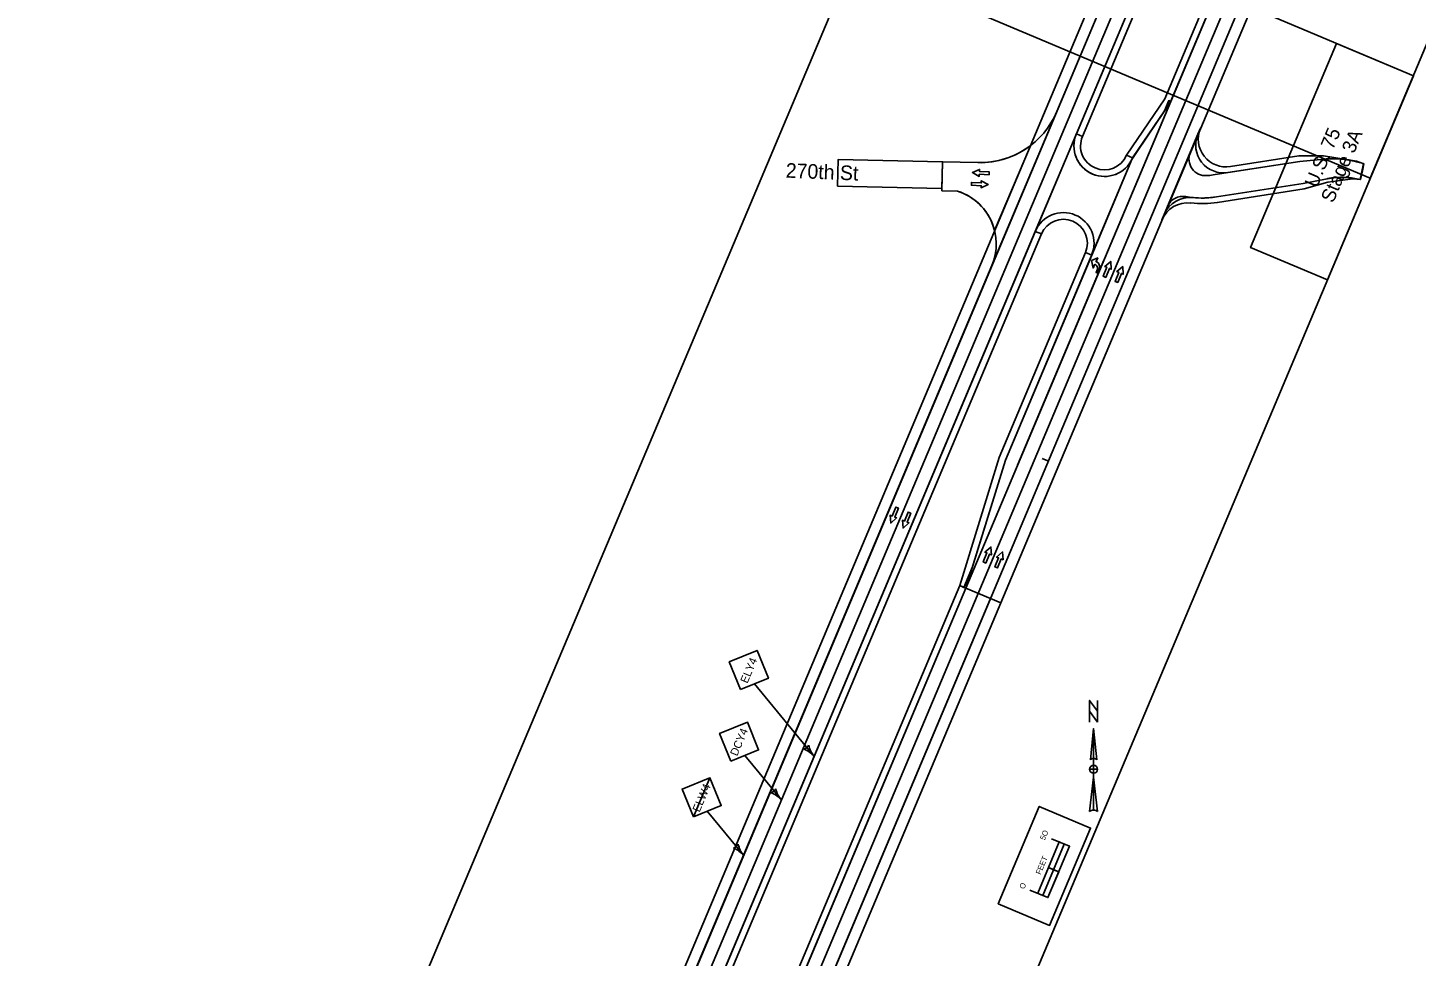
# Model space of a CAD drawing. Extents: x 14104283 to 14129344, y 8637090 to 8673339.
# Drawn here: x 14110477 to 14111726, y 8650038 to 8650873 of the extents above; entities that cross this region are included whole.
import ezdxf

# ---------------------------------------------------------------- set-up
doc = ezdxf.new("R2010")
doc.units = 0
for name, color, linetype in [('Cell', 7, 'Continuous'), ('Default', 7, 'Continuous'), ('dsnCellsNorthArrow', 7, 'Continuous'), ('dsnCellsScaleBlock', 7, 'Continuous'), ('dsnNonPlotable', 7, 'Continuous'), ('dsnPaintExistingBrokenLaneLineWhite', 7, 'Continuous'), ('dsnPaintExistingEdgeLineRightWhite', 7, 'Continuous'), ('dsnPaintExistingLaneLineWhite', 7, 'Continuous'), ('dsnPaintPlaceBrokenLineWhite', 7, 'Continuous'), ('dsnPaintPlaceEdgeLineLeftYellow', 7, 'Continuous'), ('dsnPaintPlaceEdgeLineRightWhite', 7, 'Continuous'), ('dsnShadingGranular', 7, 'Continuous'), ('dsnShadingPaved', 7, 'Continuous'), ('dsnStdLabel', 7, 'Continuous'), ('dsnStgShadingPrevPav', 7, 'Continuous'), ('dsnTextFinalPlan', 7, 'Continuous'), ('dsnTextOverlapEven', 7, 'Continuous'), ('TextAlignmentLrg', 7, 'Continuous')]:
    doc.layers.add(name, color=color, linetype=linetype)

msp = doc.modelspace()

# ---------------------------------------------------------------- linework, layer by layer
at = {"layer": 'Cell'}
for p, q in [((14111437.4, 8650659.6), (14111437.1, 8650659.8)), ((14111438.2, 8650662.2), (14111438.4, 8650662.1))]:
    msp.add_line(p, q, dxfattribs=at)
for points in [[(14111342.1, 8650742.9), (14111342, 8650740.4), (14111333.2, 8650740.8), (14111333.1, 8650738.9), (14111327, 8650742.3), (14111333.4, 8650745.1), (14111333.3, 8650743.3)], [(14111326.1, 8650730.9), (14111326.2, 8650733.4), (14111335, 8650733), (14111335, 8650734.9), (14111341.2, 8650731.5), (14111334.8, 8650728.6), (14111334.9, 8650730.5)], [(14111446.9, 8650648), (14111444.5, 8650649), (14111447.9, 8650657.1), (14111446.1, 8650657.8), (14111451.4, 8650662.4), (14111451.9, 8650655.4), (14111450.2, 8650656.1)], [(14111457.7, 8650643.5), (14111455.4, 8650644.4), (14111458.7, 8650652.5), (14111456.9, 8650653.2), (14111462.2, 8650657.8), (14111462.7, 8650650.9), (14111461, 8650651.6)], [(14111258.1, 8650441.5), (14111260.4, 8650440.5), (14111257.1, 8650432.4), (14111258.8, 8650431.7), (14111253.5, 8650427.1), (14111253, 8650434.1), (14111254.7, 8650433.4)], [(14111269.2, 8650437), (14111271.5, 8650436), (14111268.2, 8650427.9), (14111269.9, 8650427.2), (14111264.6, 8650422.6), (14111264.1, 8650429.6), (14111265.8, 8650428.9)], [(14111339, 8650391.1), (14111336.7, 8650392.1), (14111340.1, 8650400.2), (14111338.3, 8650400.9), (14111343.6, 8650405.5), (14111344.1, 8650398.5), (14111342.4, 8650399.2)], [(14111349.6, 8650386.7), (14111347.2, 8650387.7), (14111350.6, 8650395.8), (14111348.8, 8650396.5), (14111354.1, 8650401.1), (14111354.6, 8650394.1), (14111352.9, 8650394.8)]]:
    msp.add_lwpolyline(points, close=True, dxfattribs=at)
for points in [[(14111333.3, 8650743.3), (14111333.4, 8650745.1), (14111327, 8650742.3), (14111333.1, 8650738.9), (14111333.2, 8650740.8), (14111342, 8650740.4), (14111342.1, 8650742.9), (14111333.3, 8650743.3)], [(14111334.9, 8650730.5), (14111334.8, 8650728.6), (14111341.2, 8650731.5), (14111335, 8650734.9), (14111335, 8650733), (14111326.2, 8650733.4), (14111326.1, 8650730.9), (14111334.9, 8650730.5)], [(14111434, 8650663.3), (14111439.8, 8650665.5), (14111438.2, 8650662.2)], [(14111434, 8650663.3), (14111439.8, 8650665.5), (14111438.2, 8650662.2)], [(14111437.1, 8650659.8), (14111435.6, 8650656.4), (14111434, 8650663.3)], [(14111437.1, 8650659.8), (14111435.6, 8650656.4), (14111434, 8650663.3)], [(14111437.4, 8650659.6), (14111437.1, 8650659.8)], [(14111438.2, 8650662.2), (14111438.4, 8650662.1)], [(14111450.2, 8650656.1), (14111451.9, 8650655.4), (14111451.4, 8650662.4), (14111446.1, 8650657.8), (14111447.9, 8650657.1), (14111444.5, 8650649), (14111446.9, 8650648), (14111450.2, 8650656.1)], [(14111461, 8650651.6), (14111462.7, 8650650.9), (14111462.2, 8650657.8), (14111456.9, 8650653.2), (14111458.7, 8650652.5), (14111455.4, 8650644.4), (14111457.7, 8650643.5), (14111461, 8650651.6)], [(14111441, 8650655.3), (14111439.7, 8650651.9), (14111438.3, 8650652.5), (14111439.3, 8650654.9)], [(14111441, 8650655.3), (14111439.7, 8650651.9), (14111438.3, 8650652.5), (14111439.3, 8650654.9)], [(14111254.7, 8650433.4), (14111253, 8650434.1), (14111253.5, 8650427.1), (14111258.8, 8650431.7), (14111257.1, 8650432.4), (14111260.4, 8650440.5), (14111258.1, 8650441.5), (14111254.7, 8650433.4)], [(14111265.8, 8650428.9), (14111264.1, 8650429.6), (14111264.6, 8650422.6), (14111269.9, 8650427.2), (14111268.2, 8650427.9), (14111271.5, 8650436), (14111269.2, 8650437), (14111265.8, 8650428.9)], [(14111342.4, 8650399.2), (14111344.1, 8650398.5), (14111343.6, 8650405.5), (14111338.3, 8650400.9), (14111340.1, 8650400.2), (14111336.7, 8650392.1), (14111339, 8650391.1), (14111342.4, 8650399.2)], [(14111352.9, 8650394.8), (14111354.6, 8650394.1), (14111354.1, 8650401.1), (14111348.8, 8650396.5), (14111350.6, 8650395.8), (14111347.2, 8650387.7), (14111349.6, 8650386.7), (14111352.9, 8650394.8)]]:
    msp.add_lwpolyline(points, dxfattribs=at)
for centre, major_axis in [((14111436, 8650656.2), (-1.38, -3.41)), ((14111436, 8650656.2), (-1.38, -3.41)), ((14111436.4, 8650657.2), (-1.97, -4.87)), ((14111436.4, 8650657.2), (-1.97, -4.87))]:
    msp.add_ellipse(centre, major_axis=major_axis, ratio=0.9474, start_param=1.570796, end_param=3.141593, dxfattribs=at)
at = {"layer": 'Default'}
for points in [[(14118413.2, 8667444.3), (14110818.4, 8649409.2), (14109142.6, 8645431.4)], [(14109164.7, 8645422.1), (14110840.5, 8649399.8), (14118435.4, 8667434.9)]]:
    msp.add_lwpolyline(points, dxfattribs=at)
at = {"layer": 'dsnCellsNorthArrow'}
for p, q in [((14111436, 8650242.3), (14111438.8, 8650214.1)), ((14111436, 8650242.3), (14111436, 8650169)), ((14111433.2, 8650214.1), (14111433.2, 8650214.1)), ((14111433.3, 8650214.4), (14111433.8, 8650215)), ((14111432.4, 8650167.6), (14111436, 8650198.6)), ((14111436, 8650202.1), (14111436, 8650202.1))]:
    msp.add_line(p, q, dxfattribs=at)
msp.add_lwpolyline([(14111439.5, 8650247.9), (14111432.4, 8650257.8), (14111432.4, 8650267.6), (14111439.5, 8650257.8)], close=True, dxfattribs=at)
for points in [[(14111432.4, 8650247.9), (14111432.4, 8650267.6), (14111439.5, 8650257.8), (14111439.5, 8650267.6)], [(14111433.2, 8650214.1), (14111436, 8650242.3), (14111436, 8650215.5)], [(14111439.5, 8650205.7), (14111436, 8650205.7), (14111436, 8650209.2)], [(14111436, 8650202.1), (14111436, 8650205.7), (14111432.4, 8650205.7)], [(14111436, 8650169), (14111436, 8650198.6), (14111439.5, 8650167.6)]]:
    msp.add_lwpolyline(points, dxfattribs=at)
for centre, radius, start, end in [((14111436, 8650205.7), 3.52, 90, 180), ((14111436, 8650212), 3.52, 90.0204, 143.1257), ((14111436, 8650212), 3.52, 36.8481, 90.0218), ((14111436, 8650205.7), 3.52, 0, 90), ((14111436, 8650205.7), 3.52, 180, 270), ((14111436, 8650205.7), 3.52, 270, 360), ((14111436, 8650163.9), 5.1, 89.9894, 133.619), ((14111436, 8650163.9), 5.11, 46.4021, 90.0006)]:
    msp.add_arc(centre, radius, start, end, dxfattribs=at)
at = {"layer": 'dsnCellsScaleBlock'}
msp.add_line((14111404.7, 8650113.3), (14111395.5, 8650117.2), dxfattribs=at)
msp.add_line((14111404.7, 8650113.3), (14111395.5, 8650117.2), dxfattribs=at)
for points in [[(14111396.4, 8650065.3), (14111350.3, 8650084.7), (14111387.2, 8650172.2), (14111433.3, 8650152.8)], [(14111350.3, 8650084.7), (14111387.2, 8650172.2), (14111433.3, 8650152.8), (14111396.4, 8650065.3)], [(14111396.4, 8650065.3), (14111350.3, 8650084.7), (14111387.2, 8650172.2), (14111433.3, 8650152.8)], [(14111400, 8650115.3), (14111409.7, 8650138.3), (14111405.2, 8650140.3), (14111395.5, 8650117.2)], [(14111395, 8650090.3), (14111404.7, 8650113.3), (14111400, 8650115.3), (14111390.3, 8650092.2)]]:
    msp.add_lwpolyline(points, close=True, dxfattribs=at)
for points in [[(14111378.8, 8650097.1), (14111395, 8650090.3), (14111414.4, 8650136.4), (14111398.3, 8650143.2)], [(14111385.8, 8650094.2), (14111405.2, 8650140.3)]]:
    msp.add_lwpolyline(points, dxfattribs=at)
at = {"layer": 'dsnNonPlotable'}
for points in [[(14111219.5, 8650933.3), (14111828.1, 8652377.8), (14112293.5, 8652181.8), (14111684.9, 8650737.2)], [(14110649.8, 8649580.9), (14111258.3, 8651025.5), (14111723.7, 8650829.4), (14111115.1, 8649384.9)]]:
    msp.add_lwpolyline(points, close=True, dxfattribs=at)
at = {"layer": 'dsnPaintExistingBrokenLaneLineWhite'}
msp.add_line((14110829.5, 8649404.5), (14118424.3, 8667439.6), dxfattribs=at)
at = {"layer": 'dsnPaintExistingEdgeLineRightWhite'}
msp.add_line((14110924.4, 8649364.5), (14118874.7, 8668243.7), dxfattribs=at)
at = {"layer": 'dsnPaintExistingLaneLineWhite'}
msp.add_line((14111367.7, 8650479.1), (14111445.3, 8650663.4), dxfattribs=at)
at = {"layer": 'dsnPaintPlaceBrokenLineWhite'}
msp.add_line((14110913.3, 8649369.2), (14114932.5, 8658913.4), dxfattribs=at)
at = {"layer": 'dsnPaintPlaceEdgeLineLeftYellow'}
for p, q in [((14113594.8, 8655940.3), (14111420.5, 8650777)), ((14111505.3, 8650805.9), (14113533.3, 8655621.7)), ((14111470.9, 8650755.1), (14111505.3, 8650805.9)), ((14111356.7, 8650483.8), (14111434.3, 8650668.1)), ((14111321.1, 8650368.5), (14111356.7, 8650483.8)), ((14110902.3, 8649373.8), (14111321.1, 8650368.5))]:
    msp.add_line(p, q, dxfattribs=at)
msp.add_lwpolyline([(14111383.6, 8650689.4), (14110840.5, 8649399.8), (14109233.5, 8645585.3)], dxfattribs=at)
for centre, start, end in [((14111445.8, 8650766.3), 157.1633, 335.8501), ((14111408.9, 8650678.8), 67.1633, 156.8935), ((14111408.9, 8650678.8), 337.1465, 67.1633)]:
    msp.add_arc(centre, 27.5, start, end, dxfattribs=at)
at = {"layer": 'dsnPaintPlaceEdgeLineRightWhite'}
msp.add_line((14113555.5, 8655908.7), (14111402.9, 8650797.1), dxfattribs=at)
msp.add_lwpolyline([(14111344.6, 8650658.6), (14110818.4, 8649409.2), (14109217, 8645608.1)], dxfattribs=at)
at = {"layer": 'dsnShadingGranular'}
msp.add_line((14111523, 8650760.3), (14111502.5, 8650711.7), dxfattribs=at)
at = {"layer": 'dsnShadingPaved'}
for p, q in [((14111505.5, 8650806.3), (14113533.3, 8655621.7)), ((14113555.5, 8655612.4), (14110924.4, 8649364.5)), ((14111321.1, 8650368.5), (14111505.5, 8650806.3)), ((14111505.3, 8650805.7), (14111321.1, 8650368.5)), ((14111402.9, 8650797.1), (14111344.6, 8650658.6)), ((14111470.6, 8650754.6), (14111505.3, 8650805.7)), ((14111383.6, 8650689.4), (14111420.5, 8650777)), ((14111299.6, 8650726), (14111300.2, 8650752)), ((14111300.2, 8650752), (14111332, 8650751.3)), ((14111313.6, 8650725.7), (14111299.6, 8650726)), ((14111356.7, 8650483.8), (14111434.3, 8650668.1)), ((14111321.1, 8650368.5), (14111356.7, 8650483.8)), ((14110902.3, 8649373.8), (14111321.1, 8650368.5))]:
    msp.add_line(p, q, dxfattribs=at)
for centre, radius, start, end in [((14111333.8, 8650826.2), 75, 268.6633, 337.1633), ((14111445.8, 8650766.3), 27.5, 157.1801, 247.1633), ((14111445.8, 8650766.3), 27.5, 247.1633, 335.8501), ((14111298.5, 8650678), 50, 337.1633, 72.4031), ((14111408.9, 8650678.8), 27.5, 67.1633, 156.8935), ((14111408.9, 8650678.8), 27.5, 337.1465, 67.1633)]:
    msp.add_arc(centre, radius, start, end, dxfattribs=at)
at = {"layer": 'dsnStdLabel'}
for p, q in [((14111131, 8650282.4), (14111184.8, 8650217.3)), ((14111122.2, 8650218), (14111155.2, 8650178.1)), ((14111076.1, 8650162.8), (14111090.9, 8650198)), ((14111088.6, 8650167.9), (14111121.2, 8650128.3))]:
    msp.add_line(p, q, dxfattribs=at)
for points in [[(14111118.5, 8650277.3), (14111143.5, 8650287.5), (14111133.3, 8650312.5), (14111108.3, 8650302.3)], [(14111109.7, 8650212.9), (14111134.7, 8650223.1), (14111124.6, 8650248.1), (14111099.6, 8650237.9)], [(14111076.1, 8650162.8), (14111101.1, 8650173), (14111090.9, 8650198), (14111065.9, 8650187.8)]]:
    msp.add_lwpolyline(points, close=True, dxfattribs=at)
for centre, radius, start, end in [((14111172.2, 8650231.9), 8.86, 292.8385, 328.307), ((14111167.3, 8650202.4), 22.9, 40.5727, 68.6439), ((14111202.2, 8650232.2), 22.9, 192.5015, 220.5728), ((14111142.7, 8650192.7), 8.86, 292.8385, 328.307), ((14111137.8, 8650163.1), 22.9, 40.5727, 68.6439), ((14111172.6, 8650193), 22.9, 192.5015, 220.5728), ((14111108.7, 8650143), 8.86, 292.8385, 328.307), ((14111103.8, 8650113.4), 22.9, 40.5727, 68.6439), ((14111138.7, 8650143.3), 22.9, 192.5015, 220.5728)]:
    msp.add_arc(centre, radius, start, end, dxfattribs=at)
at = {"layer": 'dsnStgShadingPrevPav'}
for p, q in [((14110809.2, 8649413), (14118404, 8667448.1)), ((14118413.2, 8667444.3), (14110818.4, 8649409.2)), ((14113594.8, 8655940.3), (14111420.5, 8650777)), ((14111402.9, 8650797.1), (14113555.5, 8655908.7)), ((14113533.3, 8655621.7), (14111505.5, 8650806.3)), ((14111352.5, 8650355.3), (14113564.7, 8655608.5)), ((14111505.5, 8650806.3), (14111321.1, 8650368.5)), ((14111344.6, 8650658.6), (14111402.9, 8650797.1)), ((14111383.6, 8650689.4), (14111420.5, 8650777)), ((14111420.5, 8650777), (14111383.6, 8650689.4)), ((14111420.5, 8650777), (14111426, 8650774.7)), ((14111529.9, 8650776.7), (14111523, 8650760.3)), ((14111532.2, 8650782.1), (14111529.9, 8650776.7)), ((14111379.2, 8650766.5), (14111347, 8650690.1)), ((14111465.6, 8650758), (14111471.1, 8650755.6)), ((14111523, 8650760.3), (14111502.5, 8650711.7)), ((14111620.7, 8650757.3), (14111559.1, 8650747.7)), ((14111642.9, 8650757.4), (14111620.7, 8650757.3)), ((14111299.6, 8650726), (14111300.2, 8650752)), ((14111300.2, 8650752), (14111332, 8650751.3)), ((14111471.1, 8650755.6), (14111434.3, 8650668.1)), ((14111621.5, 8650752.4), (14111543.5, 8650740.2)), ((14111556.8, 8650742.3), (14111621.5, 8650752.4)), ((14111643.4, 8650754.4), (14111621.5, 8650752.4)), ((14111621.5, 8650752.4), (14111643.4, 8650754.4)), ((14111678.8, 8650750.4), (14111672.4, 8650752.1)), ((14111672.4, 8650752.1), (14111678.8, 8650750.4)), ((14111675.9, 8650736.2), (14111678.8, 8650750.4)), ((14111678.8, 8650750.4), (14111677.5, 8650744)), ((14111677.8, 8650744), (14111679, 8650750.3)), ((14111543.5, 8650740.2), (14111556.8, 8650742.3)), ((14111546.6, 8650720.4), (14111624.6, 8650732.6)), ((14111624.6, 8650732.6), (14111546.6, 8650720.4)), ((14111624.6, 8650732.6), (14111646.1, 8650736.8)), ((14111646.1, 8650736.8), (14111624.6, 8650732.6)), ((14111625.4, 8650727.7), (14111646.6, 8650733.8)), ((14111669.4, 8650737.2), (14111675.9, 8650736.2)), ((14111675.9, 8650736.2), (14111669.4, 8650737.2)), ((14111677.5, 8650744), (14111675.9, 8650736.2)), ((14111676.2, 8650736.1), (14111677.8, 8650744)), ((14111677.8, 8650744), (14111677.5, 8650744)), ((14111677.5, 8650744), (14111677.8, 8650744)), ((14111313.6, 8650725.7), (14111299.6, 8650726)), ((14111547.4, 8650715.5), (14111625.4, 8650727.7)), ((14111502.5, 8650711.7), (14111499.6, 8650704.6)), ((14111499.6, 8650704.6), (14111497.5, 8650699.8)), ((14111389.1, 8650687.1), (14111383.6, 8650689.4)), ((14111434.3, 8650668.1), (14111428.7, 8650670.4)), ((14111321.1, 8650368.5), (14111352.5, 8650355.3))]:
    msp.add_line(p, q, dxfattribs=at)
for points in [[(14113600.3, 8655938), (14111426, 8650774.7), (14111420.5, 8650777), (14113594.8, 8655940.3)], [(14111465.6, 8650758), (14111500, 8650808.6), (14113527.8, 8655624.1), (14113533.3, 8655621.7), (14111505.5, 8650806.3), (14111503.6, 8650807.1), (14111499.8, 8650797.8), (14111471.1, 8650755.6)], [(14111321.1, 8650368.5), (14111319.3, 8650369.3), (14111327.1, 8650387.7), (14111356.7, 8650483.8), (14111471.1, 8650755.6), (14111499.8, 8650797.8), (14111503.6, 8650807.1), (14111505.5, 8650806.3)], [(14111299.6, 8650728), (14111205.7, 8650730.2), (14111206.3, 8650754.2), (14111300.2, 8650752)], [(14109239, 8645583), (14111389.1, 8650687.1), (14111383.6, 8650689.4), (14109233.5, 8645585.3)], [(14111315.6, 8650370.9), (14111351.1, 8650486.1), (14111428.7, 8650670.4), (14111434.3, 8650668.1), (14111356.7, 8650483.8), (14111327.1, 8650387.7), (14111319.3, 8650369.3)], [(14110622.7, 8648725.7), (14111315.6, 8650370.9), (14111321.1, 8650368.5), (14110628.3, 8648723.4)], [(14110902.3, 8649373.8), (14110924.4, 8649364.5), (14111343.3, 8650359.2), (14111321.1, 8650368.5)], [(14110933.6, 8649360.6), (14111352.5, 8650355.3), (14111343.3, 8650359.2), (14110924.4, 8649364.5)]]:
    msp.add_lwpolyline(points, close=True, dxfattribs=at)
for points in [[(14111679, 8650750.3), (14111672.5, 8650752.7), (14111642.9, 8650757.4)], [(14111646.6, 8650733.8), (14111669.3, 8650736.6), (14111676.2, 8650736.1)], [(14111383.6, 8650689.4), (14110840.5, 8649399.8), (14109233.5, 8645585.3)], [(14109217, 8645608.1), (14110818.4, 8649409.2), (14111344.6, 8650658.6)]]:
    msp.add_lwpolyline(points, dxfattribs=at)
for centre, radius, start, end in [((14111445.8, 8650766.3), 21.5, 157.1633, 247.1633), ((14111552.9, 8650767), 25, 157.1633, 278.89), ((14111552.9, 8650767), 25, 157.1633, 278.89), ((14111555.2, 8650772.4), 25, 157.1633, 278.89), ((14111333.8, 8650826.2), 75, 268.6633, 307.2369), ((14111445.8, 8650766.3), 21.5, 247.1633, 337.1633), ((14111536.8, 8650754.5), 15, 157.1633, 273.9019), ((14111536.8, 8650754.5), 15, 157.1633, 273.9019), ((14111533.4, 8650804.4), 65, 273.9019, 278.89), ((14111533.4, 8650804.4), 65, 273.9019, 278.89), ((14111298.5, 8650678), 50, 14.0332, 72.4031), ((14111522.6, 8650694.9), 25, 84.3469, 157.1633), ((14111522.6, 8650694.9), 25, 84.3469, 157.1633), ((14111516.4, 8650705.9), 15, 80.1639, 157.1633), ((14111516.4, 8650705.9), 15, 80.1639, 157.1633), ((14111533.4, 8650804.4), 85, 260.1639, 278.89), ((14111533.4, 8650804.4), 85, 260.1639, 264.3457), ((14111533.4, 8650804.4), 85, 264.3457, 278.89), ((14111520.6, 8650690.1), 25, 83.5772, 157.1633), ((14111533.4, 8650804.4), 90, 263.5772, 278.89), ((14111408.9, 8650678.8), 21.5, 67.1633, 157.1633), ((14111408.9, 8650678.8), 21.5, 337.1633, 67.1633)]:
    msp.add_arc(centre, radius, start, end, dxfattribs=at)
for points in [[(14111672.4, 8650752.1), (14111671.9, 8650752.2), (14111671, 8650752.5), (14111669.6, 8650752.8), (14111668.2, 8650753.1), (14111666.7, 8650753.4), (14111665.3, 8650753.6), (14111663.9, 8650753.9), (14111662.4, 8650754.1), (14111661, 8650754.2), (14111659.5, 8650754.4), (14111658.1, 8650754.5), (14111656.6, 8650754.6), (14111655.1, 8650754.7), (14111653.7, 8650754.8), (14111652.2, 8650754.8), (14111650.7, 8650754.8), (14111649.3, 8650754.8), (14111647.8, 8650754.7), (14111646.3, 8650754.6), (14111644.8, 8650754.5), (14111643.9, 8650754.4), (14111643.4, 8650754.4)], [(14111643.4, 8650754.4), (14111643.9, 8650754.4), (14111644.8, 8650754.5), (14111646.3, 8650754.6), (14111647.8, 8650754.7), (14111649.3, 8650754.8), (14111650.7, 8650754.8), (14111652.2, 8650754.8), (14111653.7, 8650754.8), (14111655.1, 8650754.7), (14111656.6, 8650754.6), (14111658.1, 8650754.5), (14111659.5, 8650754.4), (14111661, 8650754.2), (14111662.4, 8650754.1), (14111663.9, 8650753.9), (14111665.3, 8650753.6), (14111666.7, 8650753.4), (14111668.2, 8650753.1), (14111669.6, 8650752.8), (14111671, 8650752.5), (14111671.9, 8650752.2), (14111672.4, 8650752.1)], [(14111646.1, 8650736.8), (14111646.5, 8650736.9), (14111647.3, 8650737), (14111648.4, 8650737.2), (14111649.6, 8650737.4), (14111650.7, 8650737.5), (14111651.9, 8650737.7), (14111653, 8650737.8), (14111654.2, 8650737.9), (14111655.4, 8650738), (14111656.5, 8650738), (14111657.7, 8650738), (14111658.9, 8650738.1), (14111660.1, 8650738.1), (14111661.2, 8650738), (14111662.4, 8650738), (14111663.6, 8650737.9), (14111664.7, 8650737.8), (14111665.9, 8650737.7), (14111667.1, 8650737.6), (14111668.2, 8650737.4), (14111669, 8650737.3), (14111669.4, 8650737.2)], [(14111669.4, 8650737.2), (14111669, 8650737.3), (14111668.2, 8650737.4), (14111667.1, 8650737.6), (14111665.9, 8650737.7), (14111664.7, 8650737.8), (14111663.6, 8650737.9), (14111662.4, 8650738), (14111661.2, 8650738), (14111660.1, 8650738.1), (14111658.9, 8650738.1), (14111657.7, 8650738), (14111656.5, 8650738), (14111655.4, 8650738), (14111654.2, 8650737.9), (14111653, 8650737.8), (14111651.9, 8650737.7), (14111650.7, 8650737.5), (14111649.6, 8650737.4), (14111648.4, 8650737.2), (14111647.3, 8650737), (14111646.5, 8650736.9), (14111646.1, 8650736.8)]]:
    msp.add_open_spline(points, degree=3, dxfattribs=at)
at = {"layer": 'dsnTextOverlapEven'}
for points in [[(14111723.7, 8650829.4), (14111646.3, 8650645.7), (14111577.2, 8650674.9), (14111654.6, 8650858.5)], [(14111577.2, 8650674.9), (14111654.6, 8650858.5), (14111723.7, 8650829.4), (14111646.3, 8650645.7)]]:
    msp.add_lwpolyline(points, close=True, dxfattribs=at)
at = {"layer": 'TextAlignmentLrg'}
msp.add_line((14111394.8, 8650483), (14111389.7, 8650485.2), dxfattribs=at)

# ---------------------------------------------------------------- texts
at = {"layer": 'dsnCellsScaleBlock'}
for s, p in [('5O', (14111392.1, 8650141.4)), ('FEET', (14111388.3, 8650110.5)), ('O', (14111373.6, 8650097.5))]:
    msp.add_text(s, height=5, rotation=67.1547, dxfattribs=at).set_placement(p)
at = {"layer": 'dsnStdLabel'}
for s, p in [('ELY4', (14111124.6, 8650282.4)), ('DCY4', (14111115.4, 8650217)), ('ELW4', (14111081.6, 8650166.6))]:
    msp.add_text(s, height=7.2, rotation=67.1547, dxfattribs=at).set_placement(p)
at = {"layer": 'dsnTextFinalPlan'}
msp.add_text('270th St', height=13.12, rotation=357.6374, dxfattribs=at).set_placement((14111158.9, 8650737.8))
at = {"layer": 'dsnTextOverlapEven'}
for s, p in [('U.S. 75', (14111636.9, 8650727.9)), ('Stage 3A', (14111651.5, 8650714.3))]:
    msp.add_text(s, height=12.5, rotation=67.1547, dxfattribs=at).set_placement(p)

doc.saveas('drawing.dxf')
